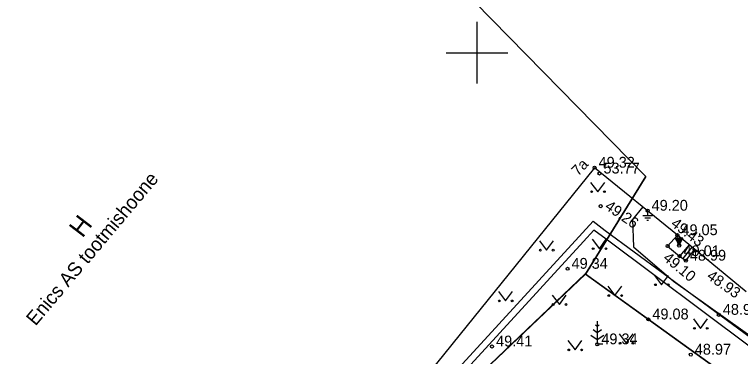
# Model space of a CAD drawing. Extents: x 640876 to 641418, y 6455595 to 6456085.
# Drawn here: x 641120.09 to 641167.04, y 6455880.34 to 6455902.47 of the extents above; entities that cross this region are included whole.
import ezdxf

# ---------------------------------------------------------------- set-up
doc = ezdxf.new("R2010")
doc.units = 0
for name, color, linetype in [('HALJASTUS', 7, 'Continuous'), ('HOONE', 7, 'Continuous'), ('HOONEDET', 7, 'Continuous'), ('KORGUS', 7, 'Continuous'), ('MOOTKORG', 7, 'Continuous'), ('MOOTMPUNKT', 7, 'Continuous'), ('MPKAABEL', 7, 'Continuous'), ('PIIR', 7, 'Continuous'), ('PUU', 7, 'Continuous'), ('SITRASS', 7, 'Continuous'), ('TTRASS', 7, 'Continuous'), ('VORK', 7, 'Continuous')]:
    doc.layers.add(name, color=color, linetype=linetype)

msp = doc.modelspace()

# ---------------------------------------------------------------- linework, layer by layer
at = {"layer": 'HALJASTUS'}
for p, q in [((641157.35, 6455891.61), (641157.814, 6455891.003)), ((641157.814, 6455891.003), (641158.259, 6455891.61)), ((641154.034, 6455887.827), (641154.497, 6455887.221)), ((641154.497, 6455887.221), (641154.943, 6455887.827)), ((641157.45, 6455887.923), (641157.914, 6455887.317)), ((641157.914, 6455887.317), (641158.359, 6455887.923)), ((641161.479, 6455885.588), (641161.942, 6455884.981)), ((641161.942, 6455884.981), (641162.388, 6455885.588)), ((641158.461, 6455884.891), (641158.924, 6455884.284)), ((641158.924, 6455884.284), (641159.37, 6455884.891)), ((641151.381, 6455884.543), (641151.845, 6455883.936)), ((641151.845, 6455883.936), (641152.29, 6455884.543)), ((641154.863, 6455884.31), (641155.326, 6455883.704)), ((641155.326, 6455883.704), (641155.772, 6455884.31)), ((641163.999, 6455882.767), (641164.462, 6455882.161)), ((641164.462, 6455882.161), (641164.908, 6455882.767)), ((641159.191, 6455881.805), (641159.654, 6455881.199)), ((641159.654, 6455881.199), (641160.1, 6455881.805)), ((641155.874, 6455881.374), (641156.338, 6455880.767)), ((641156.338, 6455880.767), (641156.783, 6455881.374))]:
    msp.add_line(p, q, dxfattribs=at)
for centre in [(641157.412, 6455891.003), (641158.241, 6455891.003), (641154.096, 6455887.221), (641154.925, 6455887.221), (641157.513, 6455887.317), (641158.341, 6455887.317), (641161.541, 6455884.981), (641162.37, 6455884.981), (641151.444, 6455883.936), (641152.272, 6455883.936), (641158.523, 6455884.284), (641159.352, 6455884.284), (641154.925, 6455883.704), (641155.754, 6455883.704), (641164.061, 6455882.161), (641164.89, 6455882.161), (641159.253, 6455881.199), (641160.082, 6455881.199), (641155.937, 6455880.767), (641156.766, 6455880.767)]:
    msp.add_circle(centre, 0.055, dxfattribs=at)
at = {"layer": 'HOONE'}
for points in [[(641167.4, 6455884.521), (641162.961, 6455888.191), (641157.603, 6455892.559), (641139.149, 6455869.673), (641123.276, 6455850.742)], [(641162.961, 6455888.191), (641162.328, 6455887.487), (641163.1, 6455886.83), (641163.505, 6455886.543), (641164.093, 6455887.255)]]:
    msp.add_lwpolyline(points, dxfattribs=at)
at = {"layer": 'HOONEDET'}
for p, q in [((641163.075, 6455887.512), (641162.829, 6455887.999)), ((641163.321, 6455887.999), (641162.829, 6455887.999)), ((641162.837, 6455887.982), (641163.181, 6455887.721)), ((641162.856, 6455887.999), (641163.192, 6455887.743)), ((641162.863, 6455887.931), (641163.169, 6455887.698)), ((641162.889, 6455887.88), (641163.158, 6455887.675)), ((641162.898, 6455887.999), (641163.204, 6455887.766)), ((641162.915, 6455887.829), (641163.146, 6455887.653)), ((641162.939, 6455887.999), (641163.215, 6455887.789)), ((641162.94, 6455887.778), (641163.135, 6455887.63)), ((641162.966, 6455887.727), (641163.123, 6455887.607)), ((641162.98, 6455887.999), (641163.227, 6455887.811)), ((641162.992, 6455887.675), (641163.112, 6455887.585)), ((641163.021, 6455887.999), (641163.238, 6455887.834)), ((641163.063, 6455887.999), (641163.249, 6455887.857)), ((641163.075, 6455887.512), (641163.321, 6455887.999)), ((641163.104, 6455887.999), (641163.261, 6455887.879)), ((641163.145, 6455887.999), (641163.272, 6455887.902)), ((641163.186, 6455887.999), (641163.284, 6455887.925)), ((641163.228, 6455887.999), (641163.295, 6455887.947)), ((641163.269, 6455887.999), (641163.307, 6455887.97)), ((641163.31, 6455887.999), (641163.318, 6455887.993)), ((641163.018, 6455887.624), (641163.1, 6455887.562)), ((641163.044, 6455887.573), (641163.089, 6455887.539)), ((641163.07, 6455887.522), (641163.077, 6455887.516)), ((641163.712, 6455887.57), (641163.1, 6455886.83)), ((641163.903, 6455887.412), (641163.302, 6455886.686))]:
    msp.add_line(p, q, dxfattribs=at)
at = {"layer": 'KORGUS'}
for centre in [(641158, 6455890.07), (641162.328, 6455887.487), (641155.856, 6455886.017), (641165.637, 6455883.038), (641161.083, 6455882.738), (641150.974, 6455880.989), (641163.825, 6455880.459)]:
    msp.add_circle(centre, 0.1, dxfattribs=at)
at = {"layer": 'MOOTMPUNKT'}
for centre in [(641157.603, 6455892.559), (641157.919, 6455892.181), (641161.032, 6455889.774), (641162.961, 6455888.191), (641163.075, 6455887.512), (641163.1, 6455886.83), (641163.505, 6455886.543), (641157.781, 6455881.129)]:
    msp.add_circle(centre, 0.1, dxfattribs=at)
at = {"layer": 'MPKAABEL'}
for points in [[(641161.032, 6455889.774), (641161.032, 6455889.435)], [(641161.35, 6455889.435), (641160.714, 6455889.435)], [(641161.216, 6455889.285), (641160.848, 6455889.285)], [(641161.082, 6455889.135), (641160.982, 6455889.135)]]:
    msp.add_lwpolyline(points, dxfattribs=at)
at = {"layer": 'PIIR'}
for points in [[(641222.58, 6455998.61), (641237.36, 6455995.24), (641235.34, 6455991.29), (641228.11, 6455971.68), (641220.5, 6455953.19), (641213.41, 6455936.25), (641201.58, 6455908.74), (641224.93, 6455905.88), (641191.87, 6455860.58), (641157.02, 6455885.66), (641160.91, 6455891.99), (641102.26, 6455951.82), (641074.95, 6455979.64), (641084.84, 6455991.92)], [(641098.62, 6455818.85), (641093.41, 6455823.22), (641084.65, 6455830.08), (641067.32, 6455843.61), (641055.55, 6455852.8), (641061.31, 6455859.9), (641051.68, 6455867.61), (641067, 6455888.54), (641060.97, 6455894.57), (641075.14, 6455914.24), (641087.11, 6455930.82), (641102.26, 6455951.82), (641160.91, 6455891.99), (641157.02, 6455885.66), (641139.49, 6455869), (641124.05, 6455849.81)], [(641216.67, 6455752.61), (641192, 6455776.86), (641152.58, 6455788.91), (641136.9, 6455789.33), (641119.28, 6455802.72), (641101.72, 6455816.27), (641098.61, 6455818.83), (641124.03, 6455849.78), (641139.51, 6455868.99), (641157, 6455885.69), (641191.84, 6455860.59), (641168.46, 6455829.03), (641191.37, 6455806.79), (641234.69, 6455771.62)]]:
    msp.add_lwpolyline(points, close=True, dxfattribs=at)
at = {"layer": 'PUU'}
for p, q in [((641157.781, 6455882.629), (641157.781, 6455881.129)), ((641157.781, 6455881.879), (641157.514, 6455882.057)), ((641157.781, 6455882.279), (641157.657, 6455882.362)), ((641157.905, 6455882.362), (641157.781, 6455882.279)), ((641158.048, 6455882.057), (641157.781, 6455881.879)), ((641157.357, 6455881.718), (641157.781, 6455881.436)), ((641157.781, 6455881.436), (641158.205, 6455881.718)), ((641158.141, 6455881.129), (641157.781, 6455881.129))]:
    msp.add_line(p, q, dxfattribs=at)
at = {"layer": 'SITRASS'}
msp.add_lwpolyline([(641160.717, 6455890.02), (641160.061, 6455889.202), (641160.124, 6455887.433), (641162.714, 6455885.215), (641168.31, 6455881.226), (641178.228, 6455873.851), (641188.611, 6455866.439), (641195.817, 6455861.122), (641198.143, 6455862.18), (641205.423, 6455869.555), (641212.959, 6455877.434), (641219.89, 6455884.166), (641222.806, 6455887.129), (641228.363, 6455892.82), (641230.103, 6455894.633)], dxfattribs=at)
at = {"layer": 'TTRASS'}
for points in [[(641146.983, 6455877.597), (641147.637, 6455878.312), (641148.076, 6455878.791), (641148.587, 6455879.349), (641156.827, 6455888.351), (641157.502, 6455889.088), (641158.299, 6455888.492), (641167.659, 6455881.582), (641177.2, 6455874.303), (641186.795, 6455867.097), (641195.745, 6455860.541), (641196.509, 6455859.853), (641197.119, 6455860.535), (641205.5, 6455869.137), (641213.939, 6455877.707), (641222.42, 6455886.169), (641230.878, 6455894.702), (641235.947, 6455899.687), (641236.146, 6455899.925), (641236.328, 6455899.987), (641239.542, 6455899.756)], [(641240.141, 6455899.285), (641236.489, 6455899.529), (641236.348, 6455899.464), (641230.948, 6455894.114), (641222.434, 6455885.667), (641213.976, 6455877.157), (641205.539, 6455868.624), (641197.23, 6455859.957), (641196.541, 6455859.328), (641186.928, 6455866.582), (641177.306, 6455873.752), (641167.696, 6455880.94), (641158.359, 6455887.923), (641157.562, 6455888.52), (641156.887, 6455887.782), (641148.647, 6455878.781), (641148.136, 6455878.223), (641147.697, 6455877.743), (641147.022, 6455877.006)]]:
    msp.add_lwpolyline(points, dxfattribs=at)
at = {"layer": 'VORK'}
for p, q in [((641150, 6455902), (641150, 6455898)), ((641148, 6455900), (641152, 6455900))]:
    msp.add_line(p, q, dxfattribs=at)

# ---------------------------------------------------------------- texts
at = {"layer": 'HOONE'}
for s, height, rotation, p in [('7a', 0.7, 46.9227, (641156.544, 6455891.972)), ('Enics AS tootmishoone', 0.9, 49.9488, (641121.452, 6455882.276)), ('H', 1.2, 52.5447, (641124.486, 6455887.962))]:
    msp.add_text(s, height=height, rotation=rotation, dxfattribs=at).set_placement(p)
at = {"layer": 'HOONEDET'}
msp.add_text(' 49.43', height=0.7, rotation=322.5693, dxfattribs=at).set_placement((641162.277, 6455888.982))
at = {"layer": 'KORGUS'}
for s, rotation, p in [(' 49.26', 325.1812, (641158, 6455890.07)), (' 49.10', 320.4672, (641161.778, 6455886.785)), (' 48.93', 324.8476, (641164.596, 6455885.564))]:
    msp.add_text(s, height=0.7, rotation=rotation, dxfattribs=at).set_placement(p)
for s, p in [(' 49.34', (641155.856, 6455886.017)), (' 49.08', (641161.083, 6455882.738)), (' 48.94', (641165.637, 6455883.038)), (' 49.41', (641150.974, 6455880.989)), (' 48.97', (641163.825, 6455880.459))]:
    msp.add_text(s, height=0.7, dxfattribs=at).set_placement(p)
at = {"layer": 'MOOTKORG'}
for s, p in [(' 49.32', (641157.603, 6455892.559)), (' 53.77', (641157.919, 6455892.181)), (' 49.20', (641161.032, 6455889.774)), (' 49.05', (641162.961, 6455888.191)), (' 49.01', (641163.1, 6455886.83)), (' 48.99', (641163.505, 6455886.543)), (' 49.34', (641157.781, 6455881.129))]:
    msp.add_text(s, height=0.7, dxfattribs=at).set_placement(p)

doc.saveas('drawing.dxf')
